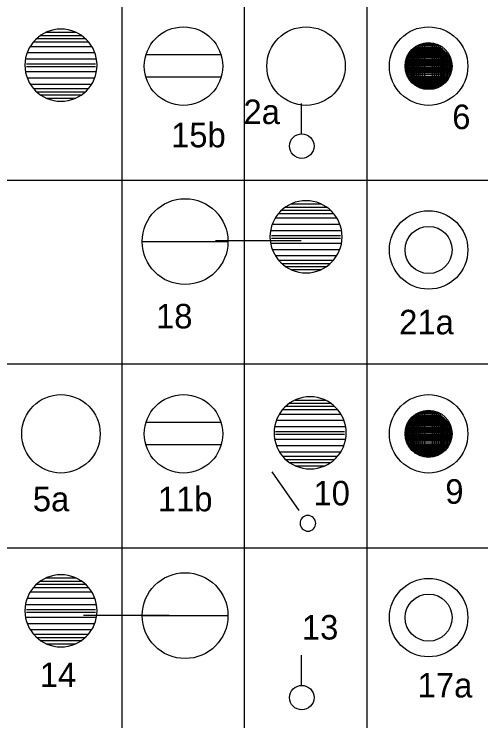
# Model space of a CAD drawing. Extents: x -28 to 822, y 61 to 665.
# Drawn here: x 361.8 to 399.9, y 142.6 to 200.3 of the extents above; entities that cross this region are included whole.
import ezdxf

# ---------------------------------------------------------------- set-up
doc = ezdxf.new("R2010")
doc.units = 0
doc.layers.add('KOLEJIŠTĚ', color=7, linetype='Continuous')

# ---------------------------------------------------------------- blocks, each defined once
blk = doc.blocks.new('HR3')
for radius in [2.5, 1.5]:
    blk.add_circle((0, 0), radius)
blk = doc.blocks.new('ZT72')
at = {"xscale": 0.8, "yscale": 0.8000000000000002}
blk.add_blockref('HR3', (0, 0), dxfattribs=at)
blk = doc.blocks.new('HR6')
for p, q in [((-1.304, 1.895), (1.304, 1.895)), ((-0.95, 2.095), (0.95, 2.095)), ((-1.748, 1.495), (1.748, 1.495)), ((-1.555, 1.695), (1.555, 1.695)), ((-1.962, 1.2), (1.962, 1.2)), ((-2.156, 0.8), (2.156, 0.8)), ((-2.265, 0.4), (2.265, 0.4)), ((-2.2, 0.09), (2.2, 0.09)), ((-2.265, -0.4), (2.265, -0.4)), ((-2.2, -0.09), (2.2, -0.09)), ((-2.156, -0.8), (2.156, -0.8)), ((-1.962, -1.2), (1.962, -1.2)), ((-1.748, -1.495), (1.748, -1.495)), ((-1.555, -1.695), (1.555, -1.695)), ((-1.304, -1.895), (1.304, -1.895)), ((-0.95, -2.095), (0.95, -2.095))]:
    blk.add_line(p, q)
for start, end in [(0, 180), (180, 0)]:
    blk.add_arc((0, 0), 2.3, start, end)
blk = doc.blocks.new('ZT75')
at = {"xscale": 0.8, "yscale": 0.8000000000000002}
blk.add_blockref('HR6', (0, 0), dxfattribs=at)
blk = doc.blocks.new('HR1')
blk.add_line((-2.5, 0), (2.5, 0))
blk.add_circle((0, 0), 2.5)

msp = doc.modelspace()

# ---------------------------------------------------------------- linework, layer by layer
for p, q in [((370.616, 381.738), (370.616, 111.738)), ((380.616, 381.738), (380.616, 111.738)), ((390.616, 381.738), (390.616, 111.738)), ((378.72, 196.957), (372.594, 196.957)), ((378.727, 195.126), (372.588, 195.126)), ((385.278, 190.441), (385.278, 192.974)), ((348.116, 186.738), (540.616, 186.738)), ((385.265, 181.767), (378.26, 181.767)), ((5.068, 171.738), (540.616, 171.738)), ((378.72, 166.957), (372.594, 166.957)), ((378.727, 165.126), (372.588, 165.126)), ((382.868, 162.92), (385.071, 159.774)), ((348.116, 156.738), (540.616, 156.738)), ((374.495, 151.207), (367.49, 151.207)), ((385.278, 145.441), (385.278, 147.974))]:
    msp.add_line(p, q)
for points in [[(396.109, 194.246), (395.145, 194.246), (395.145, 197.81), (396.109, 197.81)], [(395.955, 194.201), (395.336, 194.201), (395.336, 197.856), (395.955, 197.856)], [(396.965, 194.746), (394.299, 194.746), (394.299, 197.274), (396.965, 197.274)], [(396.865, 194.646), (394.39, 194.646), (394.39, 197.365), (396.865, 197.365)], [(396.774, 194.546), (394.471, 194.546), (394.471, 197.456), (396.774, 197.456)], [(396.665, 194.437), (394.572, 194.437), (394.572, 197.556), (396.665, 197.556)], [(396.601, 194.383), (394.708, 194.383), (394.708, 197.692), (396.601, 197.692)], [(396.437, 194.337), (394.826, 194.337), (394.826, 197.719), (396.437, 197.719)], [(396.264, 194.292), (394.972, 194.292), (394.972, 197.765), (396.264, 197.765)], [(397.374, 195.355), (393.935, 195.355), (393.935, 196.728), (397.374, 196.728)], [(397.329, 195.183), (393.971, 195.183), (393.971, 196.847), (397.329, 196.847)], [(397.302, 195.064), (394.007, 195.064), (394.007, 196.965), (397.302, 196.965)], [(397.183, 194.955), (394.071, 194.955), (394.071, 197.056), (397.183, 197.056)], [(397.092, 194.846), (394.198, 194.846), (394.198, 197.183), (397.092, 197.183)], [(397.547, 195.956), (393.78, 195.956), (393.78, 196.11), (397.547, 196.11)], [(397.484, 195.765), (393.807, 195.765), (393.807, 196.319), (397.484, 196.319)], [(397.511, 195.846), (393.807, 195.846), (393.807, 196.219), (397.511, 196.219)], [(397.465, 195.674), (393.853, 195.674), (393.853, 196.392), (397.465, 196.392)], [(397.438, 195.583), (393.871, 195.583), (393.871, 196.501), (397.438, 196.501)], [(397.411, 195.474), (393.907, 195.474), (393.907, 196.61), (397.411, 196.61)], [(396.109, 164.246), (395.145, 164.246), (395.145, 167.81), (396.109, 167.81)], [(395.955, 164.201), (395.336, 164.201), (395.336, 167.856), (395.955, 167.856)], [(396.965, 164.746), (394.299, 164.746), (394.299, 167.274), (396.965, 167.274)], [(396.865, 164.646), (394.39, 164.646), (394.39, 167.365), (396.865, 167.365)], [(396.774, 164.546), (394.471, 164.546), (394.471, 167.456), (396.774, 167.456)], [(396.665, 164.437), (394.572, 164.437), (394.572, 167.556), (396.665, 167.556)], [(396.601, 164.383), (394.708, 164.383), (394.708, 167.692), (396.601, 167.692)], [(396.437, 164.337), (394.826, 164.337), (394.826, 167.719), (396.437, 167.719)], [(396.264, 164.292), (394.972, 164.292), (394.972, 167.765), (396.264, 167.765)], [(397.374, 165.355), (393.935, 165.355), (393.935, 166.728), (397.374, 166.728)], [(397.329, 165.183), (393.971, 165.183), (393.971, 166.847), (397.329, 166.847)], [(397.302, 165.064), (394.007, 165.064), (394.007, 166.965), (397.302, 166.965)], [(397.183, 164.955), (394.071, 164.955), (394.071, 167.056), (397.183, 167.056)], [(397.092, 164.846), (394.198, 164.846), (394.198, 167.183), (397.092, 167.183)], [(397.547, 165.956), (393.78, 165.956), (393.78, 166.11), (397.547, 166.11)], [(397.484, 165.765), (393.807, 165.765), (393.807, 166.319), (397.484, 166.319)], [(397.511, 165.846), (393.807, 165.846), (393.807, 166.219), (397.511, 166.219)], [(397.465, 165.674), (393.853, 165.674), (393.853, 166.392), (397.465, 166.392)], [(397.438, 165.583), (393.871, 165.583), (393.871, 166.501), (397.438, 166.501)], [(397.411, 165.474), (393.907, 165.474), (393.907, 166.61), (397.411, 166.61)]]:
    msp.add_lwpolyline(points, close=True)
for centre, radius in [((375.657, 196.031), 3.2), ((385.657, 196.031), 3.2), ((385.31, 189.505), 1), ((365.657, 166.031), 3.2), ((375.657, 166.031), 3.2), ((385.31, 144.505), 1)]:
    msp.add_circle(centre, radius)
for start, end in [(35, 215), (215, 35)]:
    msp.add_arc((385.805, 158.726), 0.64, start, end)

# ---------------------------------------------------------------- block references
at = {"xscale": 1.4000000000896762, "yscale": 1.4000000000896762}
for p in [(375.783, 181.712), (375.783, 151.194)]:
    msp.add_blockref('HR1', p, dxfattribs=at)
at = {"layer": 'KOLEJIŠTĚ', "xscale": 1.600000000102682, "yscale": 1.600000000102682}
for name, p in [('ZT75', (365.657, 196.107)), ('ZT72', (395.657, 196.031)), ('ZT75', (385.657, 182.106)), ('ZT72', (395.657, 181.031)), ('ZT75', (385.991, 166.107)), ('ZT72', (395.657, 166.031)), ('ZT75', (365.657, 151.588)), ('ZT72', (395.657, 151.031))]:
    msp.add_blockref(name, p, dxfattribs=at)

# ---------------------------------------------------------------- texts
for s, p in [('2a', (380.552, 191.303)), ('6', (397.585, 190.894)), ('15b', (374.641, 189.408)), ('18', (373.414, 174.631)), ('21a', (393.252, 174.147)), ('10', (386.259, 160.19)), ('9', (397.019, 160.323)), ('5a', (363.362, 159.709)), ('11b', (373.561, 159.709)), ('13', (385.315, 149.245)), ('14', (363.928, 145.367)), ('17a', (394.763, 144.52))]:
    msp.add_text(s, height=2).set_placement(p)

doc.saveas('drawing.dxf')
